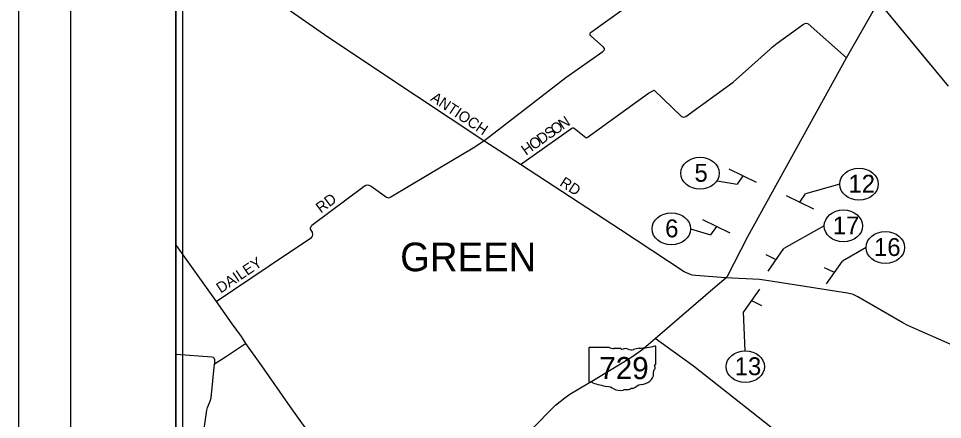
# Model space of a CAD drawing. Extents: x 0 to 784, y 0 to 440.
# Drawn here: x 0 to 176.2, y 120.2 to 196.7 of the extents above; entities that cross this region are included whole.
import ezdxf

# ---------------------------------------------------------------- set-up
doc = ezdxf.new("R2010")
doc.units = 0
for name, color, linetype in [('Default', 7, 'Continuous'), ('SH_Border', 7, 'Continuous'), ('SH_Cut_Line', 7, 'Continuous')]:
    doc.layers.add(name, color=color, linetype=linetype)

msp = doc.modelspace()

# ---------------------------------------------------------------- linework, layer by layer
at = {"layer": 'Default'}
for p, q in [((140.7, 165.41), (135.48, 167.91)), ((133.2, 165.71), (136.99, 165.08)), ((138.09, 166.66), (136.99, 165.08)), ((156.58, 165.08), (150.05, 163.23)), ((146.34, 162.9), (151.57, 160.4)), ((148.96, 161.65), (150.05, 163.23)), ((135.68, 155.74), (130.45, 158.25)), ((133.06, 156.99), (131.96, 155.42)), ((153.6, 157.12), (145.93, 152.83)), ((128.12, 156.56), (131.96, 155.42)), ((144.43, 150.67), (142.52, 151.57)), ((142.92, 148.5), (145.93, 152.83)), ((161.6, 153), (157.07, 150.39)), ((154.05, 146.06), (157.07, 150.39)), ((155.56, 148.22), (153.66, 149.13)), ((141.24, 145.03), (138.22, 140.7)), ((139.73, 142.86), (141.63, 141.95)), ((138.56, 133.3), (138.22, 140.7)), ((112.61, 133.95), (108.88, 133.95)), ((121.49, 130.76), (121.49, 134.11)), ((108.76, 133.84), (108.76, 127.44)), ((121.49, 130.76), (121.49, 130.76))]:
    msp.add_line(p, q, dxfattribs=at)
msp.add_lwpolyline([(31.33, 429.99), (465.77, 429.99), (465.77, 10.05), (31.33, 10.05)], close=True, dxfattribs=at)
for points in [[(177.35, 316.06), (100.83, 299.13), (35.04, 284.49), (73.81, 267.89), (110.52, 252.18), (116.33, 249.66), (125.29, 245.78), (143.28, 224.29), (163.94, 199.83), (177.25, 183.75)], [(30.04, 286.69), (35.04, 284.49), (73.81, 267.89), (110.52, 252.18), (116.33, 249.66), (125.29, 245.78), (143.28, 224.29), (163.94, 199.83), (173.81, 187.91)], [(134.84, 147.23), (129.05, 147.63), (128.52, 147.72), (128.27, 147.8), (126.92, 148.37), (114.76, 156.37), (95.69, 168.8), (88.72, 173.31), (75.89, 181.87), (59, 193.09), (39.44, 206.81), (37.41, 208.3)], [(98.27, 118.76), (101.8, 122.34), (102.39, 122.9), (104.17, 124.34), (105.12, 125.01), (110.27, 128.11), (114.78, 130.8), (116.58, 131.91), (117.59, 132.59), (118.83, 133.49), (120.05, 134.48), (121.4, 135.63), (133.26, 145.89), (134.84, 147.23), (135.14, 147.53), (139.03, 155.09), (157.83, 189.16), (163.94, 199.83)], [(47.78, 149.49), (47.78, 149.49), (55.89, 154.92), (56.04, 155.15), (56.12, 155.41), (56.03, 155.91), (55.68, 156.47), (55.67, 156.67), (55.72, 156.9), (55.95, 157.27), (65.9, 164.67), (66.22, 164.87), (66.61, 164.94), (66.81, 164.9), (67.24, 164.69), (70.14, 162.6), (70.34, 162.52), (70.53, 162.46), (70.75, 162.55), (70.98, 162.65), (78.2, 166.96), (86.66, 172.01), (88.72, 173.31), (91.48, 175.41), (104.37, 185.39), (111.39, 190.39), (111.65, 190.62), (111.72, 190.77), (111.72, 190.97), (111.54, 191.19), (109.16, 193.3), (109, 193.51), (108.98, 193.74), (109.04, 194), (109.63, 194.39), (111.01, 195.4), (115.48, 198.56)], [(143.36, 190.87), (143.71, 191.2), (144.65, 191.95), (149.64, 195.58), (149.99, 195.72), (150.21, 195.75), (150.53, 195.67), (157.83, 189.16)], [(136.26, 184.5), (143.36, 190.87)], [(121.19, 183), (126.41, 178.01), (126.58, 177.92), (126.87, 177.87), (127.2, 177.96), (136.26, 184.5)], [(95.69, 168.8), (105.51, 175.73), (105.69, 175.81), (105.81, 175.81), (105.97, 175.77), (108.15, 174), (108.23, 173.94), (108.44, 173.95), (120.1, 182.4), (121.19, 183)], [(30.04, 153.36), (37.68, 142.72), (40.66, 138.44), (42.44, 136), (43.27, 134.68), (46.35, 130.4), (51.75, 122.66), (53.96, 119.57), (60.87, 110.14), (61.92, 108.65), (62.35, 107.93), (62.64, 107.2), (62.93, 106.11), (62.89, 104.91), (62.73, 102.24), (62.78, 101.91), (62.84, 101.62), (63.04, 101.12)], [(37.68, 142.72), (47.78, 149.49)], [(197.74, 123.4), (197.74, 123.4), (197.04, 124.07), (196.25, 124.74), (194.14, 126.31), (192.83, 127.08), (192.25, 127.37), (191.14, 128.13), (189.48, 129.28), (189.02, 129.5), (188.12, 129.85), (176.45, 135.07), (171.86, 137.11), (169.57, 138.11), (168.61, 138.65), (160.01, 143.57), (159.12, 144.01), (158.86, 144.09), (158.05, 144.28), (143.84, 146.54), (142.19, 146.79), (141.26, 146.9), (134.84, 147.23)], [(39.45, 132.15), (43.27, 134.68)], [(159.09, 106.43), (128.7, 130.38), (121.4, 135.63)], [(30.04, 132.63), (36.85, 132.13), (37.14, 132.07), (37.25, 131.96), (37.38, 131.64), (37.4, 130.79), (39.45, 132.15), (39.45, 132.15)], [(33.9, 102.21), (33.97, 103.48), (34.66, 111.87), (35.06, 116.27), (35.91, 121.97), (36.05, 122.47), (36.56, 123.72), (36.74, 124.34), (37.4, 130.79)]]:
    msp.add_lwpolyline(points, dxfattribs=at)
for centre in [(129.93, 167.17), (160.24, 165.08), (124.46, 156.56), (157.26, 157.12), (165.26, 153), (138.56, 130.27)]:
    msp.add_ellipse(centre, major_axis=(3.66, 0), ratio=0.82844, dxfattribs=at)
for centre, major_axis, start_param, end_param in [((108.9, 133.85), (0.147, 0), 1.712693, 3.28349), ((113.5, 134.69), (1.43, 0), 4.042523, 4.731795), ((116.95, 142.68), (13.5, 0), 4.814394, 5.042369), ((121.35, 134.12), (0.142, 0), 6.141152, 7.989035), ((113.97, 130.36), (5.14, 0), 1.404758, 1.657858), ((115.14, 133.89), (0.413, 0), 3.836095, 5.185415), ((115.74, 133.15), (0.858, 0), 0.950623, 2.079405), ((116.85, 134.16), (1.03, 0), 4.081561, 5.145723), ((118.67, 132), (2.72, 0), 1.699011, 2.107814), ((121.45, 130.51), (0.219, 0), 1.883978, 3.671073), ((120.06, 130.09), (1.32, 0), 5.934695, 6.695948), ((121.34, 130.75), (0.152, 0), 5.05454, 6.418171), ((117.71, 128.93), (3.38, 0), 5.101752, 6.440018), ((122, 129.36), (0.958, 0), 2.387724, 3.262537), ((108.9, 127.42), (0.149, 0), 3.00124, 4.508301), ((108.93, 128.08), (1.14, 0), 4.665946, 4.897461), ((109.16, 127.07), (0.409, 0), 0.519207, 1.627899), ((114.33, 132.82), (9.75, 0), 4.195997, 4.488961), ((119.13, 125.64), (1.85, 0), 1.647645, 2.488434), ((111.42, 124.56), (3.05, 0), 0.823519, 1.323587), ((114.72, 127.04), (1.94, 0), 4.026481, 4.996735), ((115.84, 124.82), (1.59, 0), 1.495662, 1.94098), ((115.98, 126.56), (1.03, 0), 4.691044, 5.507374), ((116.91, 125.94), (0.29, 0), 1.147584, 2.315152), ((116.79, 126.82), (1.09, 0), 4.937069, 5.64225)]:
    msp.add_ellipse(centre, major_axis=major_axis, ratio=0.662752, start_param=start_param, end_param=end_param, dxfattribs=at)
at = {"layer": 'SH_Border'}
for points in [[(10, 430), (30, 430), (30, 10), (10, 10)], [(30, 430), (670, 430), (670, 10), (30, 10)]]:
    msp.add_lwpolyline(points, close=True, dxfattribs=at)
at = {"layer": 'SH_Cut_Line'}
msp.add_lwpolyline([(0, 0), (680, 0), (680, 440), (0, 440)], close=True, dxfattribs=at)

# ---------------------------------------------------------------- texts
at = {"layer": 'Default'}
for s, height, rotation, p in [('ANTIOCH', 2.04, 326.308, (78.41, 181.11)), ('N', 2.04, 33.5796, (103.75, 175.41)), ('O', 2.05, 35.1711, (102.3, 174.39)), ('D', 2.05, 35.1826, (99.7, 172.55)), ('S', 2.05, 35.1868, (101.17, 173.59)), ('H', 2.05, 35.1858, (96.76, 170.48)), ('O', 2.05, 35.1809, (98.23, 171.52)), ('RD', 2.033, 327.123, (103.03, 164.9)), ('RD', 2.066, 36.9205, (57.66, 159.45)), ('GREEN', 5.455, 0, (72.77, 148.47)), ('DAILEY', 2.041, 33.8343, (38.57, 144.2))]:
    msp.add_text(s, height=height, rotation=rotation, dxfattribs=at).set_placement(p)
for s, height, p in [('5', 3.41, (128.88, 165.54)), ('12', 3.406, (158.23, 163.46)), ('17', 3.406, (155.24, 155.5)), ('6', 3.41, (123.28, 154.94)), ('16', 3.406, (163.1, 151.38)), ('729', 4.219, (110.73, 127.89)), ('13', 3.406, (136.54, 128.65))]:
    msp.add_text(s, height=height, dxfattribs=at).set_placement(p)

doc.saveas('drawing.dxf')
